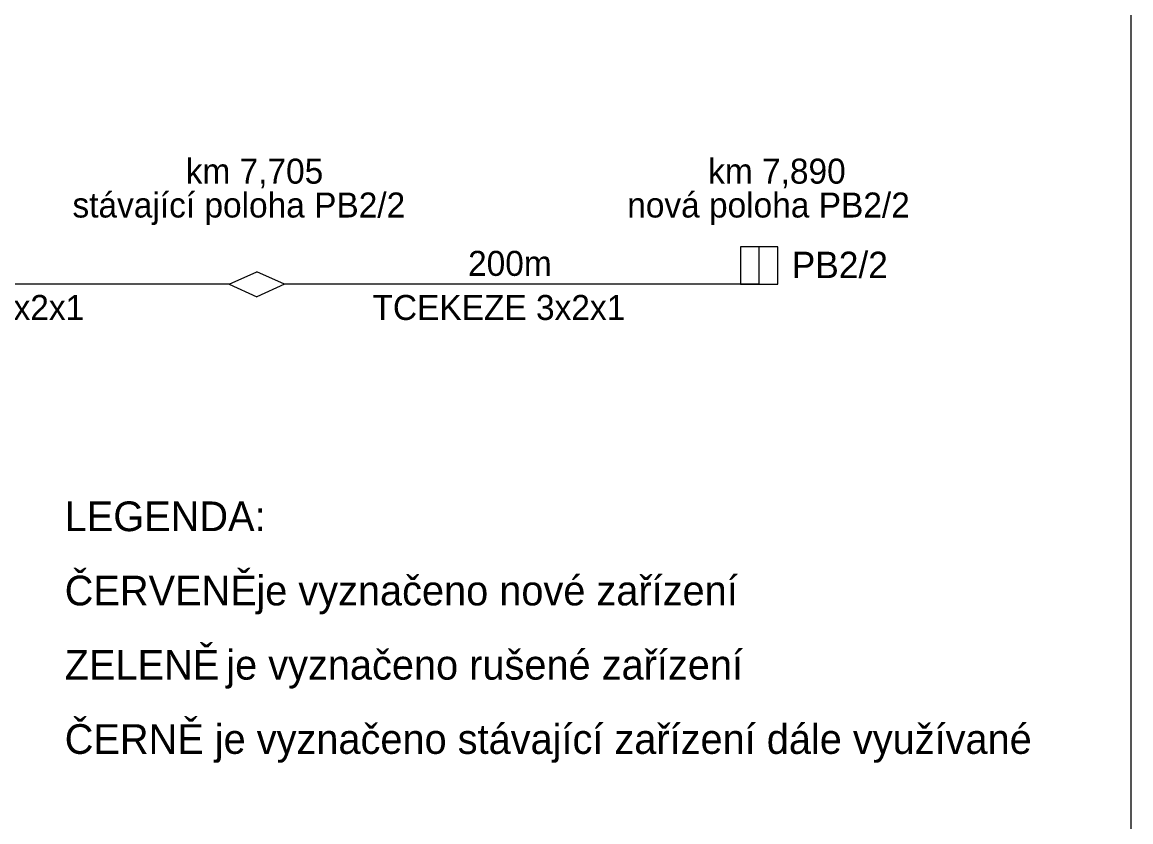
# Model space of a CAD drawing. Extents: x 6137 to 6569, y 2269 to 2566.
# Drawn here: x 6468.1 to 6556.7, y 2353.3 to 2417.3 of the extents above; entities that cross this region are included whole.
import ezdxf

# ---------------------------------------------------------------- set-up
doc = ezdxf.new("R2010")
doc.units = 0
for name, color, linetype in [('Implicitní', 7, 'Continuous'), ('kabelizace', 7, 'Continuous'), ('Schéma kabelů', 7, 'Continuous'), ('Vrstva 1', 7, 'Continuous')]:
    doc.layers.add(name, color=color, linetype=linetype)

msp = doc.modelspace()

# ---------------------------------------------------------------- linework, layer by layer
at = {"layer": 'Implicitní'}
for p, q in [((6484.604, 2396.329), (6486.824, 2397.322)), ((6489.045, 2396.329), (6486.824, 2397.322)), ((6484.604, 2396.329), (6486.824, 2395.335)), ((6489.045, 2396.329), (6486.824, 2395.335))]:
    msp.add_line(p, q, dxfattribs=at)
at = {"layer": 'kabelizace'}
msp.add_lwpolyline([(6136.73, 2565.546), (6556.73, 2565.546), (6556.73, 2268.546), (6136.73, 2268.546)], close=True, dxfattribs=at)
at = {"layer": 'Schéma kabelů'}
for p, q in [((6484.604, 2396.329), (6445.772, 2396.329)), ((6526.997, 2396.329), (6489.045, 2396.329))]:
    msp.add_line(p, q, dxfattribs=at)
for points in [[(6525.497, 2396.329), (6528.497, 2396.329), (6528.497, 2399.329), (6525.497, 2399.329)], [(6526.997, 2399.329), (6525.497, 2399.329), (6525.497, 2396.329), (6526.997, 2396.329)]]:
    msp.add_lwpolyline(points, close=True, dxfattribs=at)

# ---------------------------------------------------------------- texts
at = {"layer": 'Implicitní'}
for s, p in [('LEGENDA:', (6471.458, 2376.576)), ('ČERVENĚ', (6471.458, 2370.636)), (' je vyznačeno nové zařízení', (6485.907, 2370.636)), ('ZELENĚ', (6471.458, 2364.696)), (' je vyznačeno rušené zařízení', (6483.5, 2364.696)), ('ČERNĚ je vyznačeno stávající zařízení dále využívané', (6471.458, 2358.756))]:
    msp.add_text(s, height=2.376, dxfattribs=at).set_placement(p)
at = {"layer": 'kabelizace'}
for s, p in [(' km 7,705', (6480.393, 2404.378)), ('stávající poloha PB2/2', (6472.08, 2401.669))]:
    msp.add_text(s, height=2, dxfattribs=at).set_placement(p)
at = {"layer": 'Vrstva 1'}
for s, p in [(' km 7,890', (6522.182, 2404.378)), ('nová poloha PB2/2', (6516.45, 2401.669))]:
    msp.add_text(s, height=2, dxfattribs=at).set_placement(p)
for s, height, p in [('200m', 2, (6503.72, 2397)), ('PB2/2', 2.112, (6529.604, 2396.822)), ('TCEKEZE 3x2x1', 2, (6452.804, 2393.473)), ('TCEKEZE 3x2x1', 2, (6496.076, 2393.473))]:
    msp.add_text(s, height=height, rotation=360, dxfattribs=at).set_placement(p)

doc.saveas('drawing.dxf')
